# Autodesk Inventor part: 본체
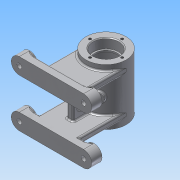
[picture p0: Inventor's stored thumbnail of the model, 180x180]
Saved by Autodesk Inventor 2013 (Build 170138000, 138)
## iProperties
Created: 2015-11
Part Number: 본체
Material: 알루미늄 6061
Document SubType Name: Modeling
Designer: Administrator
Density: 2.71 g/cm^3
Mass: 358.456 g
Surface Area: 463.793 cm^2
Volume: 132.272 cm^3
Author: Administrator
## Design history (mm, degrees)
sketch "스케치1"
  geometry: C1 r 25 at (0, 0); 1 further point
  constraints: 1 centre point, 1 coincident
  dimensions: "d0" = 50 diameter of C1
extrude "돌출1" new body sketch "스케치1" stored distance "d1" = 70; taper "d2" = 0 deg
hole "구멍1" diameter "d5" = 28; stored, may be unused: countersink angle "d9" = 90 deg, drill point angle "d11" = 0 deg; dims "d3" = 10, "d4" = 10, "d6" = 6, "d7" = 32, "d8" = 12, "d10" = 35
sketch "스케치2"
  geometry: C1 r 16 at (0, 0) reference; 1 further point
  constraints: 1 vertical alignment
  dimensions: "d12" = 20 distance of C1.centre point (0, 20)
hole "구멍2" sketch "스케치2" at (0, 20) diameter "d13" = 3.242; stored, may be unused: countersink angle "d17" = 90 deg, drill point angle "d19" = 118 deg; dims "d14" = 8, "d15" = 32, "d16" = 12, "d18" = 10
sketch "스케치3"
  geometry: C1 r 21 at (0, 0); 1 further point
  constraints: 1 centre point, 1 coincident
  dimensions: "d23" = 42 diameter of C1
extrude "돌출2" cut sketch "스케치3" stored distance "d24" = 42; taper "d25" = 0 deg
sketch "스케치4"
  geometry: L1 (0, 0)-(14, -24.249); L2 (0, 0)-(28, 0)
  constraints: 4 end point, 1 equal length, 1 horizontal
  dimensions: "d26" = 28 distance of L1.start L1.end; "d27" = 60 deg angle of L1 L2
node "작업 평면1"
sketch "스케치5"
  geometry: C1 r 6 at (0, 0); 1 further point
  constraints: 1 centre point, 1 coincident
  dimensions: "d28" = 12 diameter of C1
extrude "돌출3" join sketch "스케치5" stored distance "d29" = 42; taper "d30" = 0 deg
hole "구멍3" diameter "d33" = 5.188; stored, may be unused: countersink angle "d37" = 90 deg, drill point angle "d39" = 118 deg; dims "d31" = 10, "d32" = 10, "d34" = 8, "d35" = 32, "d36" = 12, "d38" = 10
node "작업 평면2"
sketch "스케치6"
  geometry: L1 (-40, -20)-(40, -20); L2 (-40, -40)-(40, -40); A1 r 10 centre (-40, -30) between (-40, -20) and (-40, -40); A2 r 10 centre (40, -30) between (40, -20) and (40, -40); 2 further points
  constraints: 4 end point, 4 point on circle, 4 tangent, 2 centre point, 1 horizontal alignment, 1 midpoint, 1 vertical alignment
  dimensions: "d41" = 20 diameter of A1; "d42" = 20 diameter of A2; "d43" = 80 distance of A2.centre A1.centre; "d44" = 40 distance from line of point (0, 0) L2
extrude "돌출4" join sketch "스케치6" distance "d45" = 13; taper "d46" = 0 deg
extrude "돌출5" join sketch "스케치6" distance "d47" = 10; taper "d48" = 0 deg
hole "구멍4" diameter "d51" = 6; stored, may be unused: countersink angle "d55" = 90 deg, drill point angle "d57" = 0 deg; dims "d49" = 10, "d50" = 10, "d52" = 8, "d53" = 12, "d54" = 4, "d56" = 10
hole "구멍5" diameter "d60" = 6; stored, may be unused: countersink angle "d64" = 90 deg, drill point angle "d66" = 0 deg; dims "d58" = 10, "d59" = 10, "d61" = 8, "d62" = 12, "d63" = 4, "d65" = 10
sketch "스케치7"
  geometry: L1 (-40, 20)-(40, 20) reference; L2 (-25, 28)-(25, 28); L3 (25, 28)-(25, 20); L4 (25, 20)-(-25, 20); L5 (-25, 20)-(-25, 28); 2 further points
  constraints: 8 end point, 2 midpoint, 2 parallel, 1 horizontal, 1 perpendicular
  dimensions: "d67" = 50 distance of L3.end L4.end; "d68" = 8 distance of L2.end L3.end
extrude "돌출6" join sketch "스케치7" stored distance "d69" = 10; taper "d70" = 0 deg
node "작업 평면3"
sketch "스케치8"
  geometry: L1 (25, 28)-(25, 20) reference; L2 (25, 20)-(-25, 20) reference; L3 (-25, 20)-(-25, 28) reference; L4 (-25, 28)-(25, 28) reference; L5 (25, -20)-(25, -28) reference; L6 (25, -28)-(-25, -28) reference; L7 (-25, -28)-(-25, -20) reference; L8 (-25, -20)-(25, -20) reference; L9 (-4, 20)-(-4, -20); L10 (4, 20)-(4, -20); 1 further point
  constraints: 4 end point, 4 point on line, 2 perpendicular
  dimensions: "d72" = 4 distance from line of point (0, 0) L9; "d73" = 8 distance between parallel lines of L10 L9
extrude "돌출7" join sketch "스케치8" stored distance "d74" = 10; taper "d75" = 0 deg
sketch "스케치9"
  geometry: L1 (8.5, 13.5)-(31.5, 13.5); L2 (31.5, 13.5)-(31.5, 6.5); L3 (31.5, 6.5)-(8.5, 6.5); L4 (8.5, 6.5)-(8.5, 13.5); L5 (40, -23)-(60, -23) reference; 1 further point
  constraints: 8 end point, 2 parallel, 1 horizontal, 1 perpendicular
  dimensions: "d76" = 23 distance of L2.end L3.end; "d77" = 7 distance of L1.end L2.end; "d78" = 11.5 distance from line of point (20, 45) L4; "d79" = 36.5 distance between parallel lines of L5 L1
extrude "돌출8" cut sketch "스케치9" stored distance "d80" = 10; taper "d81" = 0 deg
fillet "모깎기1" dims "d82" = 3.5
node "작업 평면4"
sketch "스케치10"
  geometry: C1 r 5 at (-40, -40); 1 further point
  constraints: 1 centre point, 1 coincident
  dimensions: "d84" = 10 diameter of C1
extrude "돌출9" join sketch "스케치10" stored distance "d85" = 10; taper "d86" = 0 deg
hole "구멍6" diameter "d89" = 5.188; stored, may be unused: countersink angle "d93" = 90 deg, drill point angle "d95" = 0 deg; dims "d87" = 10, "d88" = 10, "d90" = 8, "d91" = 12, "d92" = 4, "d94" = 10
fillet "모깎기2" dims "d96" = 0.3
chamfer "모따기1" distance "d97" = 1; stored, may be unused: second distance "d98" = 2, angle "d99" = 45 deg
fillet "모깎기3" dims "d100" = 2
fillet "모깎기5" dims "d102" = 3
node "작업 평면5"
sketch "스케치11"
  geometry: 2 further points
  constraints: 1 coincident, 1 other
feature "엠보싱1" sketch "스케치11" dims "d0" = 50, "d103" = 0.5, "d104" = 0
fillet "모깎기6" dims "d105" = 2
fillet "모깎기7" dims "d106" = 2
fillet "모깎기8" dims "d107" = 2
fillet "모깎기9" dims "d108" = 2
fillet "모깎기10" dims "d109" = 2
node "솔리드1"
pattern_circular "원형 패턴1" dims angle "d21" = 360 deg
mirror "대칭1"
mirror "대칭2"
node "절단 모서리 투영1"
other parameters: "d40" = -68, "d71" = -45, "d83" = -96
